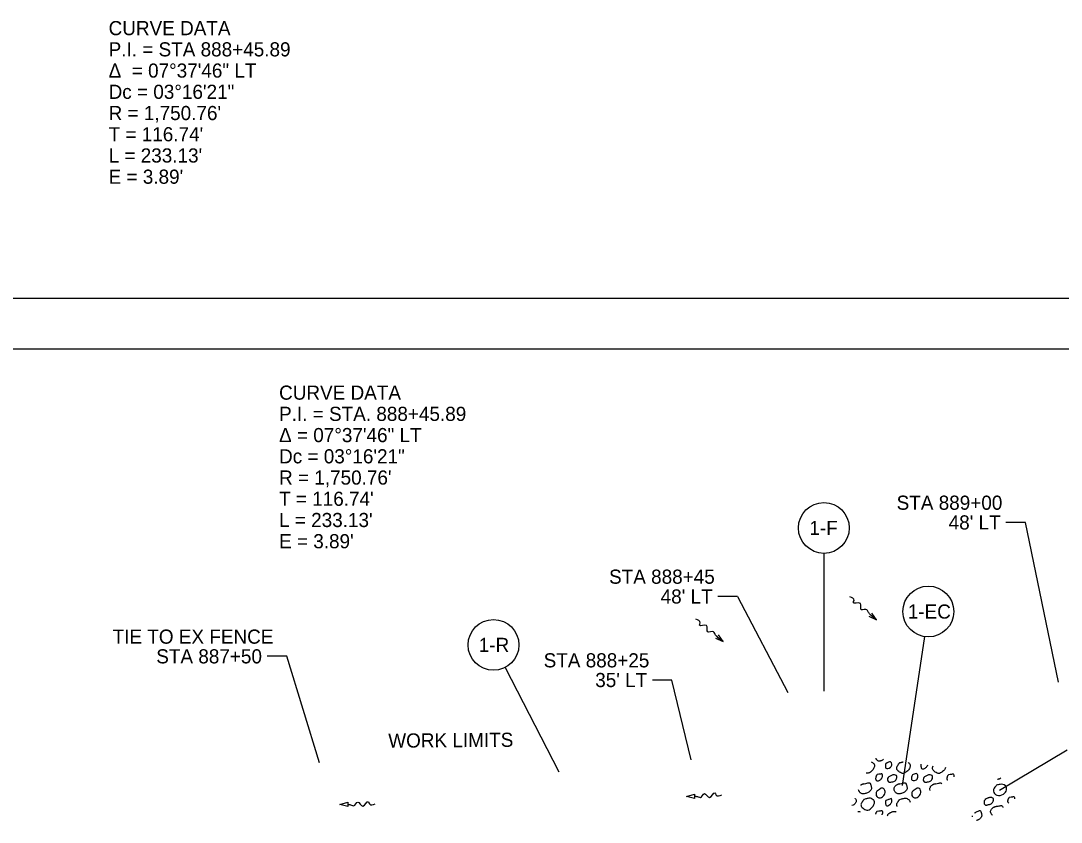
# Model space of a CAD drawing. Extents: x 0 to 2520, y -440 to 502.
# Drawn here: x 277.3 to 483.2, y 336.3 to 494.9 of the extents above; entities that cross this region are included whole.
import ezdxf

# ---------------------------------------------------------------- set-up
doc = ezdxf.new("R2010")
doc.units = 0
for name, color, linetype in [('Default', 7, 'Continuous'), ('DR_P_Culvert', 7, 'Continuous'), ('DR_X_Culvert', 7, 'Continuous'), ('MT_P_Edge_Line', 7, 'Continuous'), ('MT_P_Transverse_Line', 7, 'Continuous'), ('PF_P_Grade_Line', 7, 'Continuous'), ('TX_P_1', 7, 'Continuous'), ('XS_P_Pavt_Surface', 7, 'Continuous')]:
    doc.layers.add(name, color=color, linetype=linetype)

msp = doc.modelspace()

# ---------------------------------------------------------------- linework, layer by layer
at = {"layer": 'DR_P_Culvert'}
for points, degree in [([(445.58, 348.29), (445.72, 348.24), (445.85, 348.17), (445.98, 348.05), (446.25, 347.83), (446.27, 347.5), (446.2, 347.25), (446.11, 346.94), (445.91, 346.64), (445.61, 346.38), (445.31, 346.13), (444.93, 346), (444.59, 346.05)], 3), ([(448.07, 348.83), (447.88, 348.63), (447.67, 348.53), (447.45, 348.46), (447.26, 348.4), (447.01, 348.39), (446.83, 348.58), (446.68, 348.72), (446.59, 348.88), (446.56, 349.04)], 3), ([(452.92, 348.16), (452.96, 348.13), (453.01, 348.09), (453.05, 348.05), (453.32, 347.83), (453.34, 347.5), (453.27, 347.25), (453.18, 346.94), (452.98, 346.64), (452.68, 346.38), (452.3, 346.06), (451.77, 345.93), (451.38, 346.16), (451.07, 346.34), (450.73, 346.62), (450.67, 346.95), (450.64, 347.16), (450.74, 347.4), (450.86, 347.59), (450.95, 347.73), (451.03, 347.87), (451.14, 347.98), (451.19, 348.03), (451.25, 348.08), (451.3, 348.13)], 3), ([(451.3, 348.13), (451.51, 348.19), (451.72, 348.24), (451.93, 348.3)], 2), ([(456.75, 347.63), (456.69, 347.49), (456.59, 347.36), (456.48, 347.22), (456.26, 346.95), (455.69, 346.76), (455.58, 347.05), (455.52, 347.21), (455.51, 347.37), (455.5, 347.53), (455.5, 347.62), (455.47, 347.7), (455.51, 347.78), (455.51, 347.78), (455.52, 347.79), (455.52, 347.8)], 3), ([(460.3, 347.14), (460.2, 346.87), (460.02, 346.61), (459.75, 346.38), (459.37, 346.06), (458.84, 345.93), (458.45, 346.16), (458.14, 346.34), (457.81, 346.62), (457.74, 346.95), (457.71, 347.12), (457.78, 347.31), (457.87, 347.47)], 3), ([(444.19, 343.97), (444.49, 344.03), (444.79, 344.08), (445.1, 344.13), (445.4, 344.17), (445.54, 343.65), (445.61, 343.37), (445.68, 343.11), (445.64, 342.79), (445.42, 342.55), (445.15, 342.26), (444.86, 342.14), (444.53, 342.05), (444.25, 341.96), (443.93, 341.93), (443.65, 342.05), (443.48, 342.12), (443.36, 342.25), (443.25, 342.41), (443.19, 342.5), (443.14, 342.61), (443.12, 342.72)], 3), ([(443.55, 343.7), (443.56, 343.71), (443.58, 343.72), (443.59, 343.73), (443.74, 343.82), (443.88, 343.91), (444.04, 343.94), (444.09, 343.95), (444.15, 343.97), (444.2, 343.98)], 3), ([(446.81, 345.79), (447.07, 345.82), (447.32, 345.86), (447.57, 345.9), (447.8, 345.93), (447.85, 345.44), (447.78, 345.24), (447.7, 345.02), (447.51, 344.81), (447.3, 344.65), (447.09, 344.49), (446.65, 344.52), (446.53, 344.77), (446.45, 344.92), (446.49, 345.1), (446.53, 345.26), (446.57, 345.37), (446.58, 345.49), (446.65, 345.58), (446.7, 345.65), (446.76, 345.72), (446.81, 345.79)], 3), ([(451.26, 343.97), (451.56, 344.03), (451.87, 344.08), (452.17, 344.13), (452.47, 344.17), (452.61, 343.65), (452.69, 343.37), (452.76, 343.11), (452.71, 342.79), (452.49, 342.55), (452.23, 342.26), (451.93, 342.14), (451.6, 342.05), (451.32, 341.96), (451, 341.93), (450.72, 342.05), (450.55, 342.12), (450.43, 342.25), (450.32, 342.41), (450.15, 342.68), (450.1, 343.05), (450.25, 343.3), (450.35, 343.47), (450.49, 343.61), (450.66, 343.73), (450.81, 343.82), (450.95, 343.91), (451.11, 343.94), (451.17, 343.95), (451.22, 343.97), (451.28, 343.98)], 3), ([(457.3, 342.6), (457.21, 342.84), (457.2, 343.1), (457.32, 343.3), (457.42, 343.47), (457.56, 343.61), (457.73, 343.73), (457.88, 343.82), (458.02, 343.91), (458.18, 343.94), (458.24, 343.95), (458.29, 343.97), (458.35, 343.98)], 3), ([(458.33, 343.97), (458.63, 344.03), (458.94, 344.08), (459.24, 344.13), (459.37, 344.14), (459.48, 344.05), (459.56, 343.92)], 3), ([(460.79, 344.64), (460.74, 344.67), (460.7, 344.71), (460.67, 344.77), (460.6, 344.92), (460.63, 345.1), (460.68, 345.26), (460.71, 345.37), (460.72, 345.49), (460.79, 345.58), (460.85, 345.65), (460.9, 345.72), (460.95, 345.79)], 3), ([(460.95, 345.79), (461.21, 345.82), (461.46, 345.86), (461.72, 345.9), (461.92, 345.92), (461.99, 345.53), (461.94, 345.3)], 3), ([(471.24, 345.04), (471.07, 344.94), (470.89, 344.88), (470.71, 344.83), (470.67, 344.81), (470.63, 344.8), (470.58, 344.79)], 3), ([(442.35, 340.99), (442.36, 341), (442.37, 341), (442.38, 341), (442.54, 341.06), (442.62, 340.72), (442.63, 340.57), (442.65, 340.37), (442.5, 340.16), (442.33, 339.96), (442.21, 339.81), (441.96, 339.68), (441.76, 339.65)], 3), ([(444.23, 340.87), (444.47, 340.93), (444.7, 341), (444.94, 341.06), (445.29, 341.15), (445.64, 341.08), (445.98, 340.79), (446.25, 340.57), (446.27, 340.24), (446.2, 339.99), (446.11, 339.68), (445.91, 339.38), (445.61, 339.12), (445.23, 338.79), (444.7, 338.67), (444.31, 338.9), (443.99, 339.08), (443.66, 339.36), (443.6, 339.69), (443.56, 339.9), (443.67, 340.14), (443.79, 340.33), (443.88, 340.47), (443.95, 340.61), (444.07, 340.72), (444.12, 340.77), (444.18, 340.82), (444.23, 340.87)], 3), ([(448.5, 340.62), (448.82, 340.75), (449.14, 340.88), (449.45, 341), (449.61, 341.06), (449.69, 340.72), (449.7, 340.57), (449.72, 340.37), (449.57, 340.16), (449.41, 339.96), (449.18, 339.69), (448.62, 339.5), (448.51, 339.79), (448.45, 339.95), (448.43, 340.11), (448.43, 340.27), (448.42, 340.35), (448.39, 340.44), (448.44, 340.52), (448.46, 340.55), (448.48, 340.58), (448.5, 340.62)], 3), ([(450.76, 339.47), (450.72, 339.54), (450.69, 339.61), (450.67, 339.69), (450.64, 339.9), (450.74, 340.14), (450.86, 340.33), (450.95, 340.47), (451.03, 340.61), (451.14, 340.72), (451.19, 340.77), (451.25, 340.82), (451.3, 340.87)], 3), ([(451.3, 340.87), (451.54, 340.93), (451.78, 341), (452.01, 341.06), (452.36, 341.15), (452.71, 341.08), (453.05, 340.79), (453.23, 340.65), (453.3, 340.46), (453.3, 340.28)], 3), ([(468.19, 340.87), (468.36, 340.95), (468.53, 341.04), (468.69, 341.12), (468.88, 341.21), (469.1, 341.23), (469.3, 341.23), (469.44, 341.24), (469.58, 341.2), (469.72, 341.07), (469.84, 340.95), (469.82, 340.79), (469.79, 340.67), (469.73, 340.46), (469.65, 340.24), (469.44, 340.07), (469.24, 339.91), (469.03, 339.88), (468.82, 339.83), (468.59, 339.78), (468.33, 339.65), (468.11, 339.84), (467.97, 339.97), (467.94, 340.13), (467.94, 340.28), (467.95, 340.41), (467.96, 340.57), (468.05, 340.68), (468.09, 340.74), (468.14, 340.81), (468.19, 340.87)], 3), ([(472.85, 340.14), (472.79, 340.17), (472.74, 340.22), (472.71, 340.28), (472.63, 340.44), (472.67, 340.62), (472.71, 340.77), (472.74, 340.88), (472.76, 341.01), (472.83, 341.1), (472.88, 341.17), (472.94, 341.24), (472.99, 341.3)], 3), ([(472.99, 341.3), (473.25, 341.34), (473.5, 341.38), (473.75, 341.41), (473.91, 341.44), (473.98, 341.21), (473.99, 341)], 3), ([(442.93, 338.45), (442.99, 338.45), (443.05, 338.45), (443.12, 338.46), (443.23, 338.46), (443.34, 338.44), (443.44, 338.37)], 3), ([(446.52, 337.95), (446.53, 337.96), (446.53, 337.98), (446.53, 338), (446.57, 338.11), (446.58, 338.23), (446.65, 338.32), (446.7, 338.39), (446.76, 338.46), (446.81, 338.52)], 3), ([(446.81, 338.52), (447.07, 338.56), (447.32, 338.6), (447.57, 338.64), (447.8, 338.67), (447.85, 338.18), (447.78, 337.98), (447.76, 337.91), (447.73, 337.85), (447.68, 337.79)], 3), ([(448.84, 337.63), (448.86, 337.72), (448.88, 337.82), (448.94, 337.9), (448.99, 337.96), (449.04, 338.03), (449.09, 338.09)], 3), ([(449.09, 338.09), (449.25, 338.17), (449.42, 338.26), (449.59, 338.34), (449.77, 338.43), (449.99, 338.45), (450.19, 338.46), (450.31, 338.46), (450.42, 338.44), (450.53, 338.36)], 3), ([(466.04, 338.14), (466.14, 338.2), (466.23, 338.26), (466.33, 338.33)], 2), ([(466.33, 338.33), (466.56, 338.43), (466.8, 338.53), (467.03, 338.63), (467.27, 338.73), (467.39, 338.2), (467.45, 337.95), (467.5, 337.69), (467.43, 337.4), (467.22, 337.14), (467.02, 336.9), (466.8, 336.79), (466.56, 336.72), (466.52, 336.71), (466.49, 336.7), (466.46, 336.69)], 3), ([(469.62, 337.7), (469.55, 337.76), (469.49, 337.84), (469.43, 337.93), (469.26, 338.19), (469.21, 338.56), (469.36, 338.82), (469.46, 338.98), (469.59, 339.13), (469.77, 339.24), (469.91, 339.34), (470.06, 339.42), (470.22, 339.46), (470.27, 339.47), (470.33, 339.48), (470.38, 339.49)], 3), ([(470.37, 339.49), (470.67, 339.54), (470.97, 339.6), (471.28, 339.64), (471.47, 339.67), (471.59, 339.47), (471.68, 339.25)], 3), ([(465.66, 337.41), (465.65, 337.46), (465.66, 337.5), (465.67, 337.55), (465.67, 337.57), (465.68, 337.59), (465.68, 337.62)], 3)]:
    msp.add_open_spline(points, degree=degree, dxfattribs=at)
for points in [[(448.5, 347.88), (449.45, 348.26), (449.7, 347.83), (449.41, 347.22), (448.51, 347.05), (448.43, 347.53), (448.44, 347.78), (448.5, 347.88)], [(453.88, 345.79), (454.65, 345.9), (454.85, 345.24), (454.37, 344.65), (453.6, 344.77), (453.61, 345.26), (453.72, 345.58), (453.88, 345.79)], [(449.09, 345.35), (449.59, 345.6), (450.19, 345.72), (450.61, 345.56), (450.68, 345.15), (450.34, 344.56), (449.71, 344.32), (449.01, 344.33), (448.83, 344.76), (448.94, 345.16), (449.09, 345.35)], [(456.16, 345.35), (456.66, 345.6), (457.26, 345.72), (457.68, 345.56), (457.75, 345.15), (457.41, 344.56), (456.78, 344.32), (456.08, 344.33), (455.91, 344.76), (456.01, 345.16), (456.16, 345.35)], [(447.22, 342.81), (447.92, 343.11), (448.34, 342.43), (448.11, 341.62), (447.45, 341.2), (446.83, 341.32), (446.56, 342.04), (446.85, 342.57), (447.22, 342.81)], [(454.29, 342.81), (454.99, 343.11), (455.41, 342.43), (455.19, 341.62), (454.52, 341.2), (453.9, 341.32), (453.63, 342.04), (453.92, 342.57), (454.29, 342.81)], [(470.41, 343.65), (471.12, 343.84), (472.16, 343.57), (472.38, 342.77), (471.79, 341.9), (470.49, 341.68), (469.78, 342.47), (469.97, 343.11), (470.25, 343.49), (470.41, 343.65)]]:
    msp.add_spline(points, degree=3, dxfattribs=at)
at = {"layer": 'DR_X_Culvert'}
msp.add_lwpolyline([(0, 0), (680, 0), (680, 440), (0, 440)], close=True, dxfattribs=at)
at = {"layer": 'MT_P_Edge_Line'}
for p, q in [((436.24, 389.56), (436.24, 362.28)), ((456.16, 373.07), (451.72, 343.62)), ((373.15, 366.96), (383.75, 346.31)), ((484.42, 350.61), (471.03, 342.63))]:
    msp.add_line(p, q, dxfattribs=at)
at = {"layer": 'MT_P_Transverse_Line'}
for p, q in [((445.15, 377.09), (446.64, 376.36)), ((446.64, 376.36), (445.71, 377.74)), ((414.81, 372.75), (416.32, 372.08)), ((416.32, 372.08), (415.35, 373.42))]:
    msp.add_line(p, q, dxfattribs=at)
for points in [[(446.64, 376.36), (445.39, 377.46), (444.99, 378), (444.77, 378.39), (443.65, 378.39), (443.46, 379.65), (442.07, 379.77), (442.2, 380.25), (441.36, 380.96)], [(416.32, 372.08), (415.03, 373.13), (414.62, 373.66), (414.38, 374.04), (413.26, 374), (413.03, 375.26), (411.64, 375.32), (411.75, 375.81), (410.89, 376.5)]]:
    msp.add_spline(points, degree=3, dxfattribs=at)
at = {"layer": 'PF_P_Grade_Line'}
for p, q in [((476.13, 395.67), (472.27, 395.67)), ((482.71, 364.07), (476.13, 395.67)), ((419.12, 381.02), (415.27, 381.02)), ((419.12, 381.02), (429.13, 362.01)), ((329.91, 369.17), (326.05, 369.17)), ((336.43, 348.12), (329.91, 369.17)), ((406.17, 364.48), (402.31, 364.48)), ((409.96, 348.68), (406.17, 364.48))]:
    msp.add_line(p, q, dxfattribs=at)
for centre in [(436.24, 394.58), (456.91, 378.03), (370.85, 371.43)]:
    msp.add_circle(centre, 5.03, dxfattribs=at)
at = {"layer": 'TX_P_1'}
msp.add_lwpolyline([(30, 430), (670, 430), (670, 10), (30, 10)], close=True, dxfattribs=at)
at = {"layer": 'XS_P_Pavt_Surface'}
for p, q in [((409.04, 341.4), (410.61, 341.91)), ((410.61, 341.91), (410.66, 341.05)), ((340.4, 339.82), (341.99, 340.29)), ((342.01, 339.43), (340.4, 339.82)), ((341.99, 340.29), (342.01, 339.43)), ((410.66, 341.05), (409.04, 341.4))]:
    msp.add_line(p, q, dxfattribs=at)
for points in [[(410.64, 341.48), (410.7, 341.48), (411.37, 341.37), (411.79, 341.25), (412.6, 342.03), (413.61, 341.26), (414.68, 342.14), (414.93, 341.71), (416.03, 341.78)], [(342, 339.86), (342.07, 339.86), (342.73, 339.72), (343.15, 339.59), (343.98, 340.34), (344.97, 339.54), (346.07, 340.39), (346.3, 339.95), (347.4, 339.99)]]:
    msp.add_spline(points, degree=3, dxfattribs=at)

# ---------------------------------------------------------------- texts
at = {"layer": 'Default'}
for s, p in [('CURVE DATA', (294.66, 492.08)), ('P.I. = STA 888+45.89', (294.66, 487.88)), ('Δ  = 07°37\'46" LT', (294.66, 483.68)), ('Dc = 03°16\'21"', (294.66, 479.48)), ("R = 1,750.76'", (294.66, 475.28)), ("T = 116.74'", (294.66, 471.08)), ("L = 233.13'", (294.66, 466.88)), ("E = 3.89'", (294.66, 462.68))]:
    msp.add_text(s, height=2.8, dxfattribs=at).set_placement(p)
at = {"layer": 'PF_P_Grade_Line'}
for s, p in [('CURVE DATA', (328.4, 419.95)), ('P.I. = STA. 888+45.89', (328.4, 415.75)), ('Δ = 07°37\'46" LT', (328.4, 411.55)), ('Dc = 03°16\'21"', (328.4, 407.35)), ("R = 1,750.76'", (328.4, 403.15)), ("T = 116.74'", (328.4, 398.95)), ('STA 889+00', (450.64, 398.17)), ("L = 233.13'", (328.4, 394.75)), ('1-F', (433.37, 393.18)), ("48' LT", (460.94, 394.27)), ("E = 3.89'", (328.4, 390.55)), ('STA 888+45', (393.72, 383.53)), ("48' LT", (403.93, 379.62)), ('1-EC', (452.84, 376.63)), ('TIE TO EX FENCE', (295.45, 371.67)), ('1-R', (367.92, 370.03)), ('STA 887+50', (304.09, 367.77)), ('STA 888+25', (380.77, 366.98)), ("35' LT", (390.98, 363.08))]:
    msp.add_text(s, height=2.8, dxfattribs=at).set_placement(p)
msp.add_text('WORK LIMITS', height=2.8, rotation=0.4335, dxfattribs=at).set_placement((350.02, 351.08))

doc.saveas('drawing.dxf')
